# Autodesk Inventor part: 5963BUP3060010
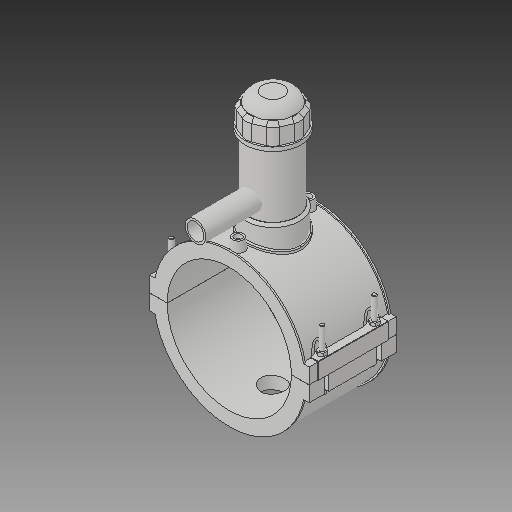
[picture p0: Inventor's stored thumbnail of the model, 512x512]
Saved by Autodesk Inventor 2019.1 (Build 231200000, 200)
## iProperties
Created: 2017-07
Part Number: 5963BUP3060010
Material: Generic
Description: PLASSON TAPPING SADDLE 6''IPS x 1''CTS
Document SubType Name: Modeling
Designer: KIM
Density: 1 g/cm^3
Appearance: Default
Author: KIM
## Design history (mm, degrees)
derived "5963BBP_5963BUP.ipt"
feature "Solid1::5963BBP_5963BUP.ipt"
feature "Solid2::5963BBP_5963BUP.ipt"
feature "Solid3::5963BBP_5963BUP.ipt"
tag "TaggingFeature1"
body "Solid1"
body "Solid2"
body "Solid3"
other parameters: "d0" = 168, "d2" = 215.9, "d3" = 42, "d4" = 118.11, "d5" = 0, "d6" = 0.1, "d8" = 0, "d19" = 6, "d20" = 6, "d21" = 70.866, "d23" = 0, "d24" = 35.433, "d26" = 0, "d27" = 3, "d28" = 3, "d29" = 3, "d30" = 56, "d31" = 6, "d32" = 0, "d33" = 0, "d34" = 0.6, "d40" = 104.832, "d41" = 75.6, "d43" = 0, "d45" = 0, "d47" = 171.666, "d70" = 15, "d72" = 0, "d73" = 6, "d75" = 5, "d76" = 0, "d77" = 8.4, "d78" = 114, "d79" = 15, "d80" = 47.244, "d82" = 5 deg, "d84" = 4, "d85" = 14, "d86" = 0, "d87" = 3, "d88" = 0, "d89" = 1, "d90" = 1, "d91" = 94.488, "d92" = 0, "d93" = 0.5, "d94" = 88.42105, "d96" = 205.632, "d97" = 2.3622, "d98" = 0, "d102" = 1.68, "d120" = 140 deg, "d121" = 24.228, "d122" = 20 deg, "d123" = 403.2, "d124" = 120.96, "d126" = 0, "d143" = 173.04, "d145" = 25.84615, "d149" = 2.52, "d150" = 28.43077, "d153" = 118.11, "d154" = 0, "d156" = 100.8, "d157" = 160 deg, "d159" = 6.72, "d161" = 2.52, "d162" = 70.866, "d163" = 0, "d164" = 84, "d167" = 16.8, "d168" = 98.34146, "d170" = 3.2805, "d172" = 0, "d173" = 1, "d175" = 84, "d176" = 20 deg, "d177" = 11.76, "d178" = 33.6, "d180" = 0, "d183" = 13.44, "d184" = 9.408, "d185" = 38.38575, "d186" = 38.38575, "d187" = 100.8, "d188" = 10.08, "d189" = 11.76, "d190" = 0, "d191" = 151.2, "d193" = 6.9984, "d194" = 4.13385, "d195" = 90 deg, "d197" = 0, "d199" = 0, "d200" = 16.8, "d202" = 0, "d203" = 177.038, "d204" = 71.82, "d205" = 52.92, "d206" = 64.26, "d207" = 132.7785, "d208" = 138.08964, "d209" = 164.64534, "d210" = 65.016, "d211" = 75.6, "d212" = 60.48, "d213" = 45.7191, "d216" = 0, "d217" = 16.8, "d218" = 16.8, "d219" = 3.36, "d222" = 168, "d224" = 0, "d225" = 65.024, "d226" = 28.45, "d227" = 22.76, "d228" = 104.902, "d230" = 5.04, "d_" = 168, "B_" = 215.9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
